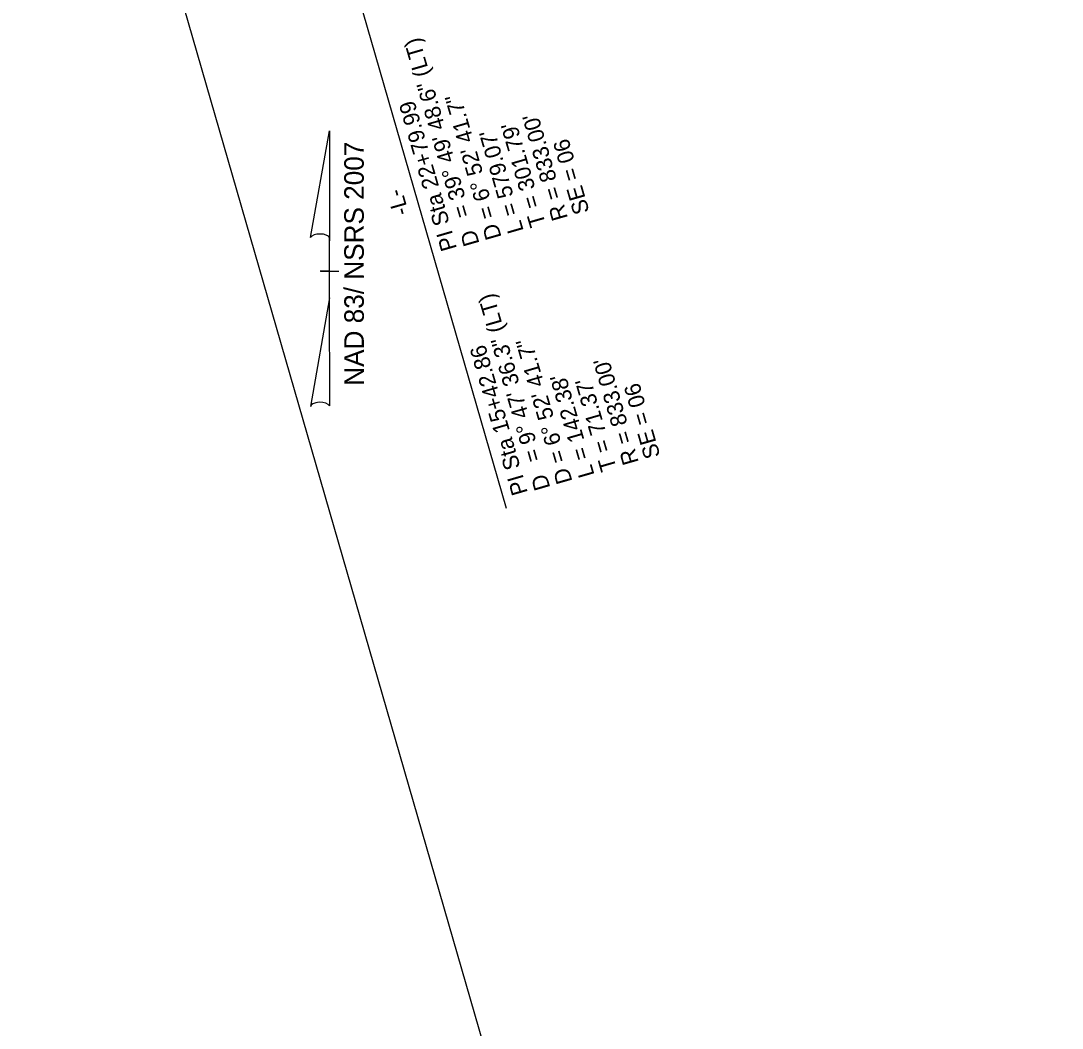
# Model space of a CAD drawing. Extents: x 2167182 to 2168576, y 842635 to 844493.
# Drawn here: x 2167182.4 to 2167635.1, y 843360.4 to 843798.4 of the extents above; entities that cross this region are included whole.
import ezdxf

# ---------------------------------------------------------------- set-up
doc = ezdxf.new("R2010")
doc.units = 0
for name, color, linetype in [('Prop Horizontal Alignment Curve and Spiral Data', 7, 'Continuous'), ('Prop North Arrow for Plan Sheets CELL', 7, 'Continuous'), ('Prop North Arrow NAD83 for Plan Sheets CELL', 7, 'Continuous'), ('Sheet Layout Plan Border', 7, 'Continuous')]:
    doc.layers.add(name, color=color, linetype=linetype)

msp = doc.modelspace()

# ---------------------------------------------------------------- linework, layer by layer
at = {"layer": 'Prop Horizontal Alignment Curve and Spiral Data'}
msp.add_line((2167393.49, 843586.34), (2167304.09, 843896), dxfattribs=at)
at = {"layer": 'Prop North Arrow for Plan Sheets CELL'}
for p, q in [((2167308.38, 843704.27), (2167316.58, 843750.62)), ((2167316.63, 843750.62), (2167316.58, 843750.62)), ((2167316.63, 843750.62), (2167316.58, 843750.62)), ((2167316.63, 843750.62), (2167316.63, 843702.82)), ((2167316.63, 843678.02), (2167316.63, 843704.22)), ((2167316.63, 843702.82), (2167316.63, 843704.17)), ((2167312.63, 843689.62), (2167312.58, 843689.62)), ((2167316.18, 843689.62), (2167312.63, 843689.62)), ((2167312.68, 843689.62), (2167320.68, 843689.62)), ((2167316.63, 843678.02), (2167308.28, 843630.77)), ((2167316.68, 843630.97), (2167316.63, 843678.02))]:
    msp.add_line(p, q, dxfattribs=at)
for centre, start_param, end_param in [((2167312.51, 843703.78), 0.216388, 2.908219), ((2167312.51, 843630.61), 0.201328, 3.141593)]:
    msp.add_ellipse(centre, major_axis=(4.23, -0.03), ratio=0.461098, start_param=start_param, end_param=end_param, dxfattribs=at)
at = {"layer": 'Sheet Layout Plan Border'}
msp.add_lwpolyline([(2168191.21, 844341.01), (2167182.42, 844049.75), (2167182.42, 844049.75), (2167567.43, 842716.21), (2168576.23, 843007.46)], close=True, dxfattribs=at)

# ---------------------------------------------------------------- texts
at = {"layer": 'Prop Horizontal Alignment Curve and Spiral Data'}
for s, p in [('= 39%%d 49\' 48.6" (LT)', (2167378.01, 843713.87)), ('D = 6%%d 52\' 41.7"', (2167391.46, 843704.38)), ('PI Sta 22+79.99', (2167372.06, 843699.48)), ("R = 833.00'", (2167420.29, 843712.7)), ("T = 301.79'", (2167410.68, 843709.93)), ("L = 579.07'", (2167401.07, 843707.16)), ('SE = 06', (2167429.67, 843715.41)), ('-L-', (2167351.15, 843714.88)), ('D', (2167381.86, 843701.61)), ('= 9%%d 47\' 36.3" (LT)', (2167408.81, 843607.67)), ('PI Sta 15+42.86', (2167402.86, 843593.28)), ('D = 6%%d 52\' 41.7"', (2167422.26, 843598.18)), ("R = 833.00'", (2167451.08, 843606.5)), ("L = 142.38'", (2167431.87, 843600.95)), ("T = 71.37'", (2167441.48, 843603.72)), ('SE = 06', (2167460.47, 843609.21)), ('D', (2167412.65, 843595.4))]:
    msp.add_text(s, height=7, rotation=106.1034, dxfattribs=at).set_placement(p)
at = {"layer": 'Prop North Arrow NAD83 for Plan Sheets CELL'}
msp.add_text('NAD 83/ NSRS 2007', height=8.5, rotation=90.0239, dxfattribs=at).set_placement((2167331.54, 843639.75))

doc.saveas('drawing.dxf')
